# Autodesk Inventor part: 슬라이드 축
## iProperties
Created: 2012-05
Part Number: 슬라이드 축
Document SubType Name: 모델링
Designer: SeoGD™
Mass: 169.555 g
Surface Area: 67.5855 cm^2
Volume: 21.5719 cm^3
Density: 7.86 g/cm^3
Material: 강, 연강
변환 표준: STEP AP214IS
파일 이름: C:\Users\SeoGD\Desktop\?쒗뿕\異?stp
전처리기: Build: 253, Release: 2010 SP1 - Date: Wed 07/29/2009
전송 단위: 밀리미터
불확실성: 0.01
Author: SeoGD™
